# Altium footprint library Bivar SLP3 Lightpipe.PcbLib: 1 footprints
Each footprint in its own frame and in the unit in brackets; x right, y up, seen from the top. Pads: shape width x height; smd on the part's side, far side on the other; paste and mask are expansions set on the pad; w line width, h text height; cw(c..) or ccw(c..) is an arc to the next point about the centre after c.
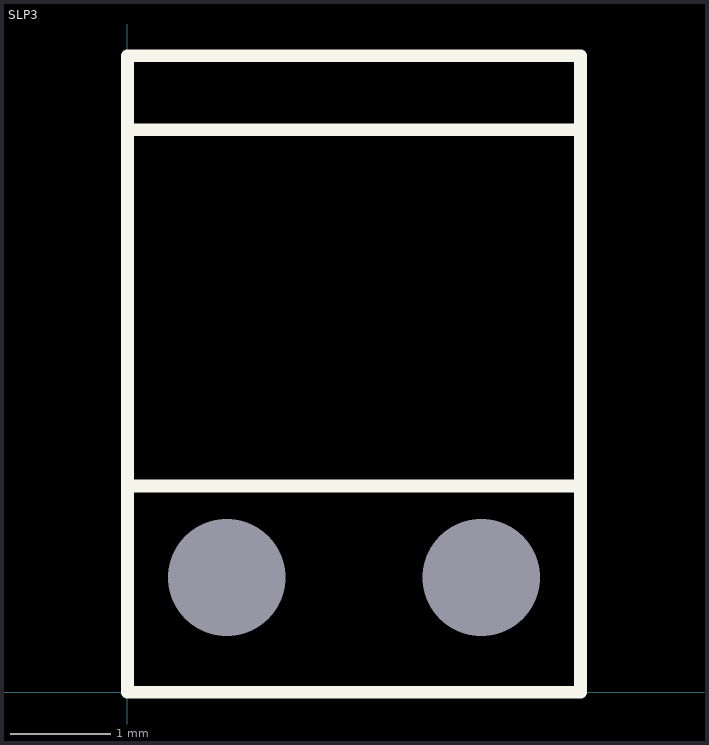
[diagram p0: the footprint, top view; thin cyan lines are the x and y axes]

## SLP3 [mil]
pads (2):
  round 0 hole 46: ""(39,45) ""(139,45)
Top Overlay:
  lines w5: 0,81 178,81 ; 0,221 178,221 ; 0,0 0,250 178,250 178,0 0,0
